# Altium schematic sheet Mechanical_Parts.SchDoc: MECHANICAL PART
size A4; Date: Not used; ApprovedBy: Not used; CheckedBy: Not used; Author: Not used; CompanyName: STMicroelectronics; DrawnBy: Not used; Engineer: Not used; Organization: Not used; Address1: Not used; Address2: Not used; Address3: Not used; Address4: Not used; DocumentNumber: 16; Revision: Not used; SheetNumber: 16; SheetTotal: 16
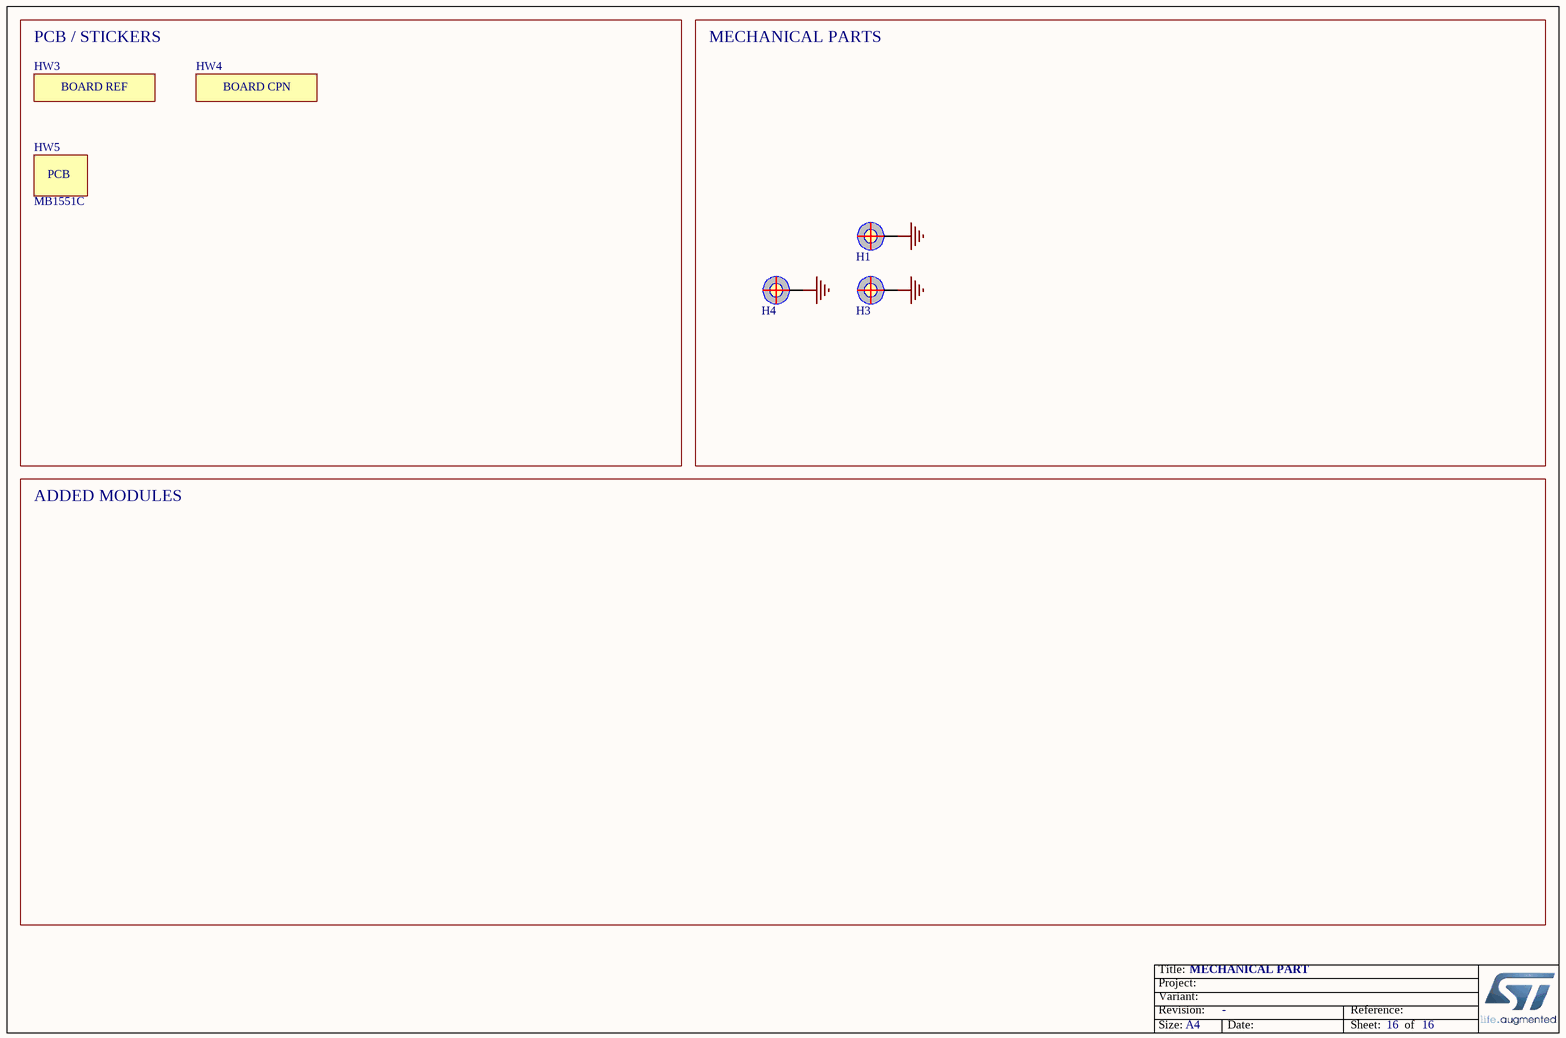
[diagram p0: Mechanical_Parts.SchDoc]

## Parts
H1  (no value)  [PTH_M1261-3005-N_3P5X6_M3_H14]  (no BOM)
H3  (no value)  [PTH_M1261-3005-N_3P5X6_M3_H14]  (no BOM)
H4  (no value)  [PTH_M1261-3005-N_3P5X6_M3_H14]  (no BOM)
HW3  (no value)  [STICKER_BOARD-REF_25X5]  (mechanical)
HW4  (no value)  [STICKER_BOARD-CPN_25X5]  (mechanical)
HW5  value MB1551C  (mechanical)

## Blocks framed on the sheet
PCB / STICKERS: HW3-HW5
MECHANICAL PARTS: H1 H3 H4

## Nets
GND: H1.1 H3.1 H4.1

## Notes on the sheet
- ADDED MODULES

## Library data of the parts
H1 H3 H4 = MCD-00035: POSITION HOLE C6D3R5; Part_Type: Mechanical; Initial_Board_Reference: MB1274
HW3 = MCD-00235: Sticker to mention board reference + serial number; Part_Type: Mechanical; Manufacturer_Part_Number: NA; Provided_By: Subcon; Initial_Board_Reference: MB1319
HW4 = MCD-00547: Sticker to mention board CPN code; Part_Type: Mechanical; Manufacturer_Part_Number: NA; Provided_By: Subcon; Initial_Board_Reference: MB1319; Remark: PCH W35 footprint requested to have a space on board for stickers.
HW5 = MCD-00216: PCB, xxxx for PCB ref, Y for revision; Part_Type: Mechanical; Provided_By: Subcon; Initial_Board_Reference: MB1319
